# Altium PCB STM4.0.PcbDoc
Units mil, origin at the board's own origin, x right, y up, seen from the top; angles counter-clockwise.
Board outline 3545 x 2170 mil, 2 copper layers (Top Layer, Bottom Layer); 59 components, 66 nets, 302 pads, 59 vias.
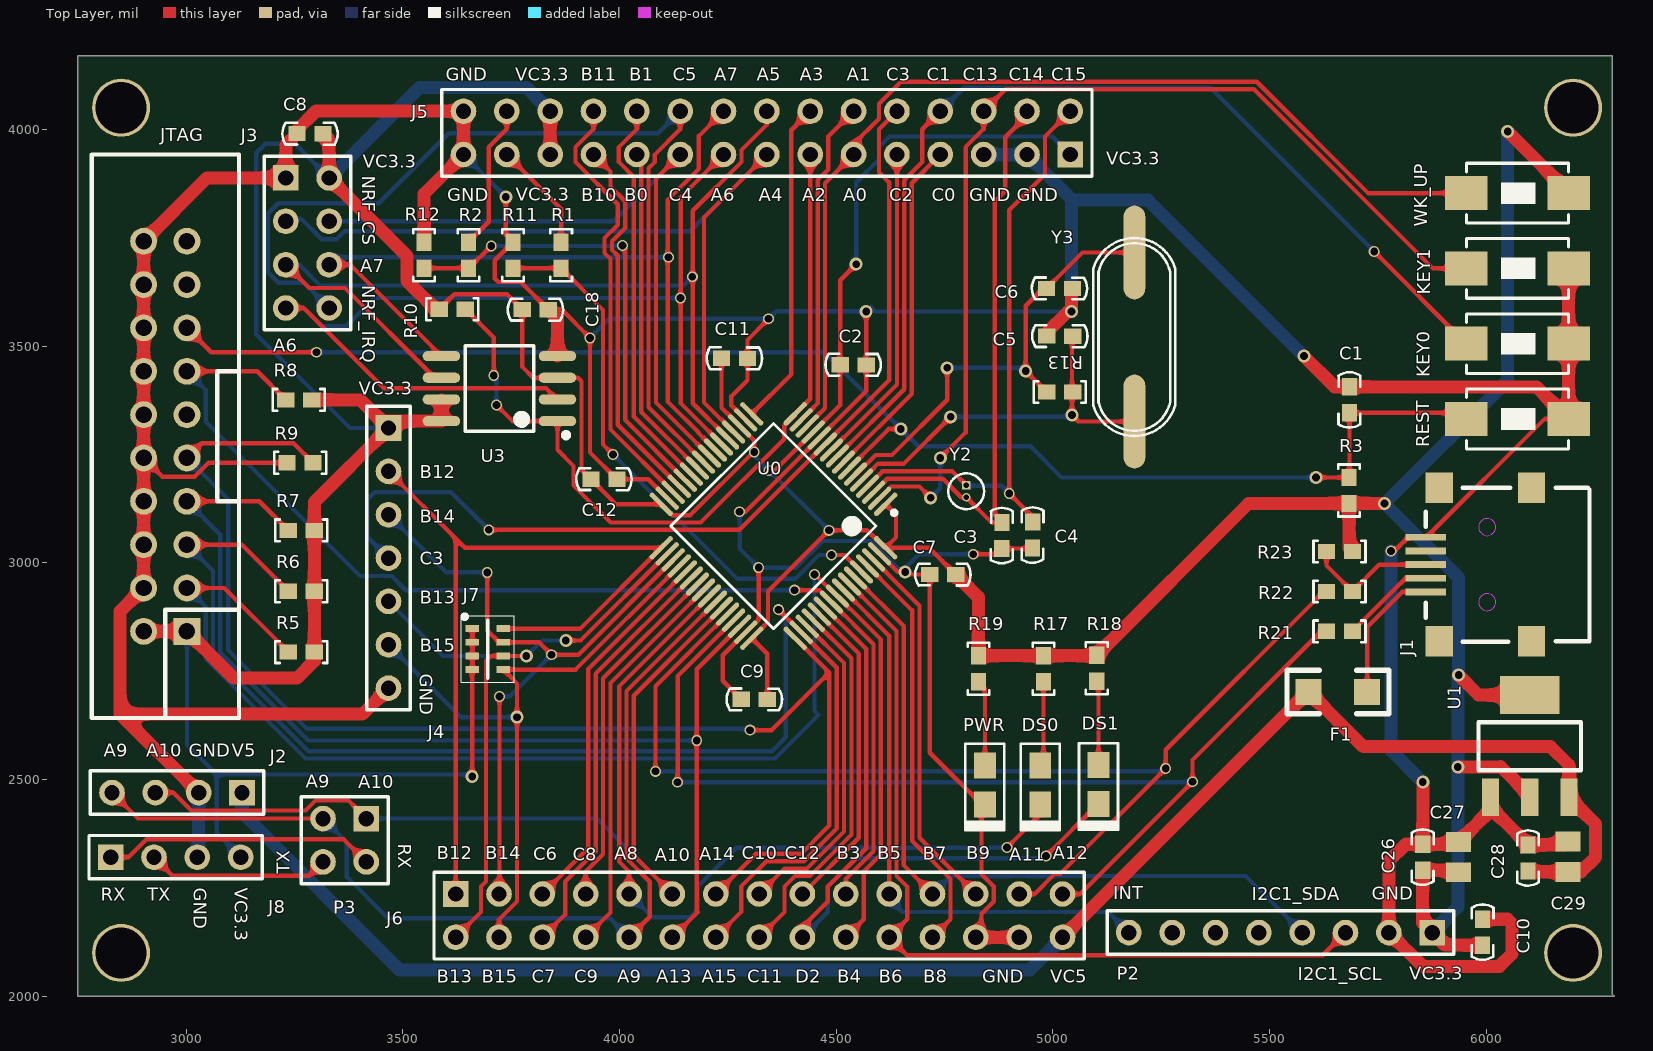
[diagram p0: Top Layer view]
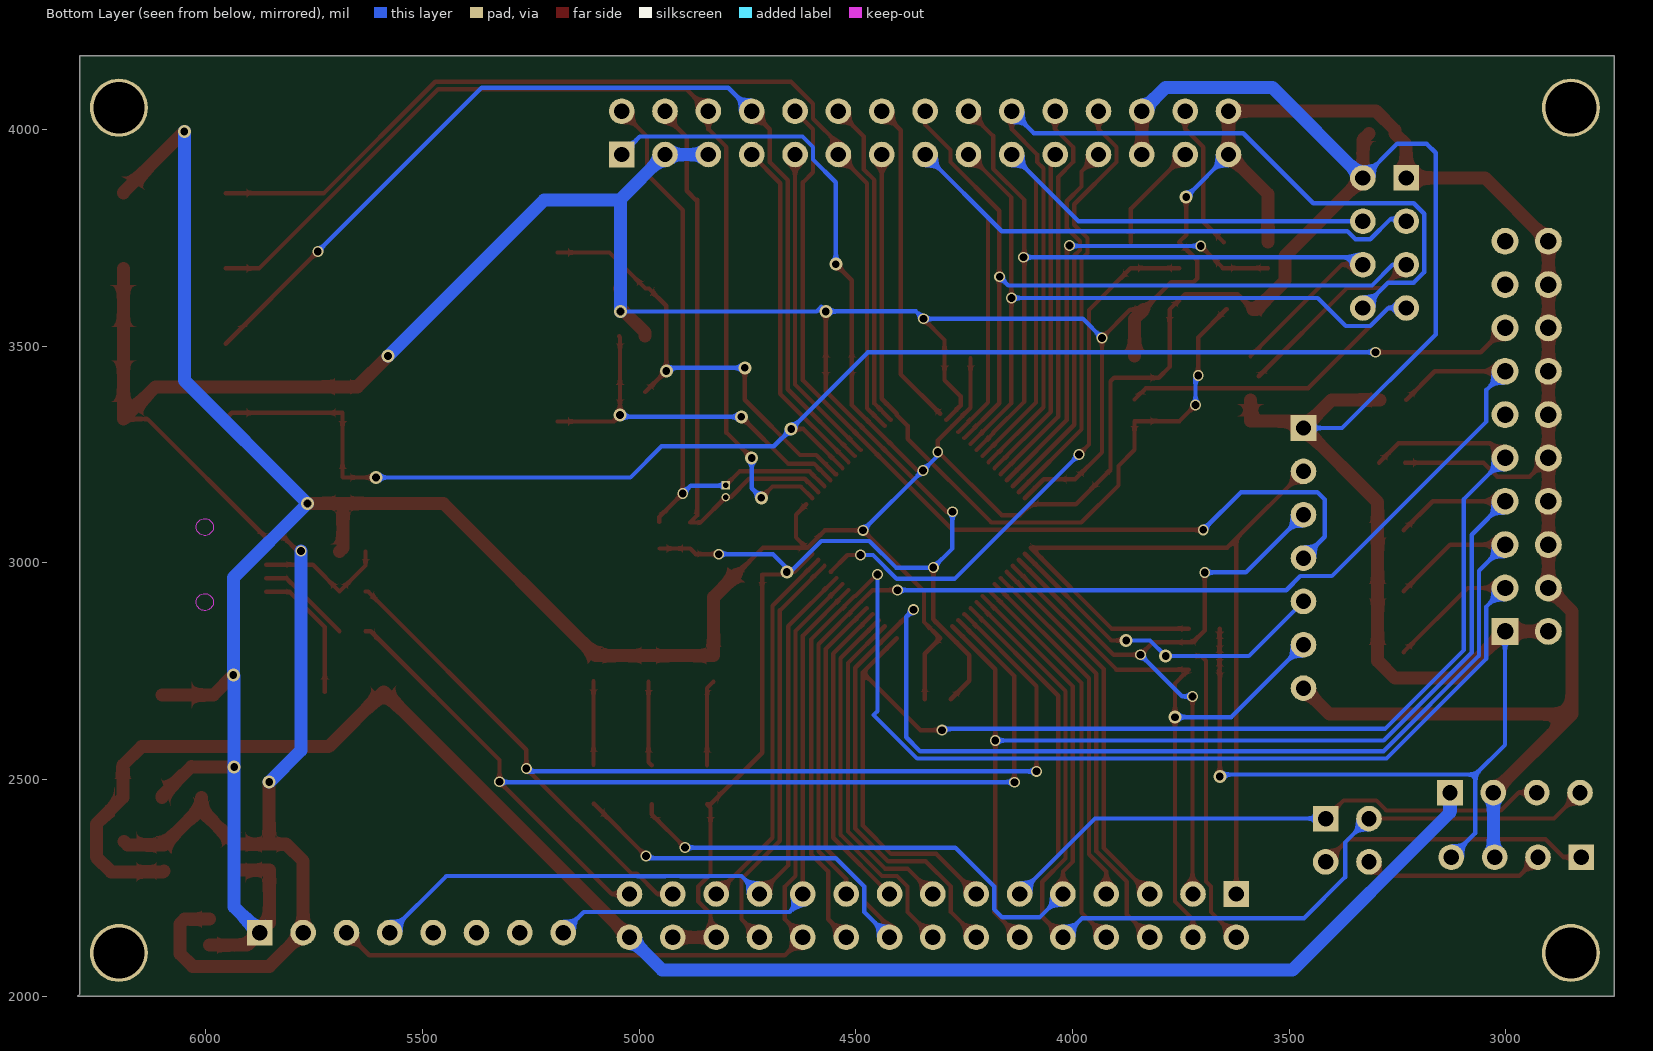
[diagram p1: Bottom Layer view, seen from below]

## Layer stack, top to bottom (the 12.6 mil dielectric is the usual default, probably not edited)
Top Solder: solder mask 0.4, Solder Resist, Dk 3.5
Top Layer: signal copper 1.4
Dielectric 1: dielectric 12.6, FR-4, Dk 4.8
Bottom Layer: signal copper 1.4
Bottom Solder: solder mask 0.4, Solder Resist, Dk 3.5

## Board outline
2750,4170 2750,2000 6295,2000 6290,2005 6290,4170 2750,4170

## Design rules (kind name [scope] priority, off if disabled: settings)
Clearance [All] p1: gap=7
PolygonConnect [All] p1: connectstyle=Relief reliefconductorwidth=10 reliefentries=4 polygonreliefangle="90 Angle" airgapwidth=10
RoutingVias [All] p1: holewidth=28 width=50 viastyle="Through Hole" minholewidth=28 minwidth=50 maxholewidth=28 maxwidth=50
SolderMaskExpansion [All] p1: expansion=4
Width [All] p1: maxlimit=30 minlimit=10 preferedwidth=10
30 further rules are at their usual default settings.

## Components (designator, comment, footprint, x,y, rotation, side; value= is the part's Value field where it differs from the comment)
C1 "Cap_0603" C0603 5684,3376 r90 top
C2 "Cap_0603" C0603 4539,3457 r0 top
C3 "CAP_0603" C0603 4882,3063 r90 top
C4 "CAP_0603" C0603 4953,3064 r90 top
C5 "Cap_0603" C0603 5015.89,3522.98 r0 top
C6 "Cap_0603" C0603 5015,3633 r0 top
C7 "Cap_0603" C0603 4746,2973 r180 top
C8 "Cap_0603" C0603 3286,3990 r180 top
C9 "Cap_0603" C0603 4311,2685 r180 top
C10 "Cap_0603" C0603 5991,2148 r270 top
C11 "Cap_0603" C0603 4265,3472 r0 top
C12 "Cap_0603" C0603 3964,3193 r0 top
C18 "Cap_0603" C0603 3806,3584 r180 top
C26 "Cap_0603" C0603 5853,2321 r90 top
C27 "106" LC-0805 5936,2321 r90 top
C28 "Cap_0603" C0603 6096,2319 r90 top
C29 "106" LC-0805 6188,2322 r90 top
DS0 "GREEN" SMD0805_LED_green 4971,2533 r270 top
DS1 "GREEN" SMD0805_LED_green 5105,2534 r270 top
F1 "500mA" FUSE_SMD1206 5590,2702 r0 top
J1 "usb" "MINI USB" 5860,2933 r180 top
J2 "USART1" HDR1X4 3129,2470 r180 top
J3 "NRF2401" HDR2X4 3230,3888 r270 top
J4 "OLED" HDR1X7 3467,3311 r270 top
J5 "Header 15X2" IDE15X2_2.54 5040,3942 r180 top
J6 "Header 15X2" IDE15X2_2.54 3622,2236 r0 top
J7 "Res_0603*4" RES_0603*4 3696,2801 r0 top
J8 "排母_2.54mm_4P" HDR1X4 2826,2321 r0 top
JTAG "10X2H" IDC20 3002,2842 r90 top
KEY0 "轻触开关/3x6x5 耐高温 环保" SW 5954.52,3505.67 r90 top
KEY1 "轻触开关/3x6x5 耐高温 环保" SW 5954.52,3679.33 r90 top
P2 "mpu6050" HDR1X8 5875,2147 r180 top
P3 "Header 2X2" HDR2X2 3416,2410 r180 top
PWR "RED" SMD0805_LED_green 4843,2533 r270 top
R1 "Res_0603" Res_0603 3865.33,3680 r90 top
R2 "Res_0603" Res_0603 3651.33,3740 r270 top
R3 "Res_0603" Res_0603 5683,3197 r270 top
R5 "Res_0603" Res_0603 3296,2794 r180 top
R6 "Res_0603" Res_0603 3296,2934.5 r180 top
R7 "Res_0603" Res_0603 3296,3075 r180 top
R8 "Res_0603" Res_0603 3290,3376 r180 top
R9 "Res_0603" Res_0603 3233,3231 r0 top
R10 "Res_0603" Res_0603 3644,3585 r180 top
R11 "Res_0603" Res_0603 3754,3740 r270 top
R12 "Res_0603" Res_0603 3549,3740 r270 top
R13 "Res_0603" Res_0603 4985.71,3393.98 r0 top
R17 "Res_0603" Res_0603 4978,2726 r90 top
R18 "Res_0603" Res_0603 5101,2727 r90 top
R19 "Res_0603" Res_0603 4828,2726 r90 top
R21 "Res_0603" Res_0603 5631,2842 r0 top
R22 "Res_0603" Res_0603 5631,2934 r0 top
R23 "Res_0603" Res_0603 5691,3026 r180 top
REST "轻触开关/3x6x5 耐高温 环保" SW 5954.52,3332 r90 top
U0 "STM32F103RCT6" LQFP64 4614,3135 r225 top
U1 "AMS1117-3.3" LC-SOT-223 6100,2577 r270 top
U3 "W25X16" LC-SOP-8_208mil 3723,3402 r90 top
WK_UP "轻触开关/3x6x5 耐高温 环保" SW 5954.52,3853 r90 top
Y2 "32.768KHZ±20ppm" TC-26 4800,3179 r270 top
Y3 "49SMD" 49SMD 5188,3521 r270 top

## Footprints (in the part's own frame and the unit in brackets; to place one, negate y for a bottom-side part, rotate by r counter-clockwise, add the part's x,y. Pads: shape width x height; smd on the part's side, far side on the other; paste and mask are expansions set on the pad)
49SMD [mil]
  oval 216.53x50 smd: 1(-195,0) 2(195,0)
  silkscreen extent -228,-95 228,94, body extent -264,-96 264,96, height 157
C0603 [mil]
  rect 40x35 smd: 1(-29.9,0.02) 2(30.1,-0.19)
  silkscreen extent -64,-25 64,25, body extent -31,-16 32,16, height 12
FUSE_SMD1206 [mil]
  rect 60x60 smd: 1(0,0) 2(135,0)
  silkscreen extent -50,-50 185,50, body extent 2,-33 128,33, height 40
HDR1X4 [mm]
  rect 1.5x1.5 hole 0.9: 1(0,0)
  round 1.5 hole 0.9: 2(2.54,0) 3(5.08,0) 4(7.62,0)
  silkscreen extent -1.27,-1.27 8.89,1.27, body extent -1.27,-1.27 8.89,1.27, height 8.38
HDR1X7 [mm] "Connector; Header; 7 Position"
  rect 1.5x1.5 hole 0.9: 1(0,0)
  round 1.5 hole 0.9: 2(2.54,0) 3(5.08,0) 4(7.62,0) 5(10.16,0) 6(12.7,0) 7(15.24,0)
  silkscreen extent -1.27,-1.27 16.51,1.27
HDR1X8 [mm]
  rect 1.5x1.5 hole 0.9: 1(0,0)
  round 1.5 hole 0.9: 2(2.54,0) 3(5.08,0) 4(7.62,0) 5(10.16,0) 6(12.7,0) 7(15.24,0) 8(17.78,0)
  silkscreen extent -1.27,-1.27 19.05,1.27, body extent -1.27,-1.27 19.05,1.27, height 8.38
HDR2X2 [mm] "Connector; Header; 2x2 Position"
  rect 1.5x1.5 hole 0.9: 1(0,0)
  round 1.5 hole 0.9: 2(0,2.54) 3(2.54,0) 4(2.54,2.54)
  silkscreen extent -1.27,-1.27 3.81,3.81
HDR2X4 [mm]
  rect 1.5x1.5 hole 0.9: 1(0,0)
  round 1.5 hole 0.9: 2(0,2.54) 3(2.54,0) 4(2.54,2.54) 5(5.08,0) 6(5.08,2.54) 7(7.62,0) 8(7.62,2.54)
  silkscreen extent -1.27,-1.27 8.89,3.81
IDC20 [mil]
  rect 62x62 hole 38: 1(0,0)
  round 62 hole 38: 2(0,100) 3(100,0) 4(100,100) 5(200,0) 6(200,100) 7(300,0) 8(300,100) 9(400,0) 10(400,100) 11(500,0) 12(500,100) 13(600,0) 14(600,100) 15(700,0) 16(700,100) 17(800,0) 18(800,100) 19(900,0) 20(900,100)
  silkscreen extent -200,-120 1100,220
IDE15X2_2.54 [mm]
  rect 1.5x1.5 hole 0.9: 1(0,0)
  round 1.5 hole 0.9: 2(0,-2.54) 3(2.54,0) 4(2.54,-2.54) 5(5.08,0) 6(5.08,-2.54) 7(7.62,0) 8(7.62,-2.54) 9(10.16,0) 10(10.16,-2.54) 11(12.7,0) 12(12.7,-2.54) 13(15.24,0) 14(15.24,-2.54) 15(17.78,0) 16(17.78,-2.54) 17(20.32,0) 18(20.32,-2.54) 19(22.86,0) 20(22.86,-2.54) 21(25.4,0) 22(25.4,-2.54) 23(27.94,0) 24(27.94,-2.54) 25(30.48,0) 26(30.48,-2.54) 27(33.02,0) 28(33.02,-2.54) 29(35.56,0) 30(35.56,-2.54)
  silkscreen extent -1.27,-3.81 36.83,1.27
LC-0805 [mm]
  rect 1.16x1.47 smd: 1(-0.89,0) 2(0.89,0)
LC-SOP-8_208mil [mm]
  oval 0.6x2.2 smd: 1(-1.905,-3.4) 2(-0.635,-3.4) 3(0.635,-3.4) 4(1.905,-3.4) 5(1.905,3.4) 6(0.635,3.4) 7(-0.635,3.4) 8(-1.905,3.4)
  silkscreen extent -2.88,-4.05 2.5,2
LC-SOT-223 [mm]
  rect 2.2x1 smd: 1(3,-2.3) 2(3,0) 3(3,2.3)
  rect 2.2x3.5 smd: 2(-3,0)
  silkscreen extent -1.4,-3 1.4,3, body extent -3.49,-3.24 3.49,3.24, height 1.64
LQFP64 [mm]
  oval 1.8x0.3 smd: 1(0,0) 2(0,-0.5) 3(0,-1) 4(0,-1.5) 5(0,-2) 6(0,-2.5) 7(0,-3) 8(0,-3.5) 9(0,-4) 10(0,-4.5) 11(0,-5) 12(0,-5.5) 13(0,-6) 14(0,-6.5) 15(0,-7) 16(0,-7.5) 33(11.1,-7.5) 34(11.1,-7) 35(11.1,-6.5) 36(11.1,-6) 37(11.1,-5.5) 38(11.1,-5) 39(11.1,-4.5) 40(11.1,-4) 41(11.1,-3.5) 42(11.1,-3) 43(11.1,-2.5) 44(11.1,-2) 45(11.1,-1.5) 46(11.1,-1) 47(11.1,-0.5) 48(11.1,0)
  oval 0.3x1.8 smd: 17(1.8,-9.3) 18(2.3,-9.3) 19(2.8,-9.3) 20(3.3,-9.3) 21(3.8,-9.3) 22(4.3,-9.3) 23(4.8,-9.3) 24(5.3,-9.3) 25(5.8,-9.3) 26(6.3,-9.3) 27(6.8,-9.3) 28(7.3,-9.3) 29(7.8,-9.3) 30(8.3,-9.3) 31(8.8,-9.3) 32(9.3,-9.3) 49(9.3,1.8) 50(8.8,1.8) 51(8.3,1.8) 52(7.8,1.8) 53(7.3,1.8) 54(6.8,1.8) 55(6.3,1.8) 56(5.8,1.8) 57(5.3,1.8) 58(4.8,1.8) 59(4.3,1.8) 60(3.8,1.8) 61(3.3,1.8) 62(2.8,1.8) 63(2.3,1.8) 64(1.8,1.8)
  silkscreen extent -0.12,-8 9.8,0.82, body extent 0.55,-8.75 10.55,1.25, height 1.6
"MINI USB" [mm]
  rect 1.6x1.8 smd: 0(-6.2,2.9) 0(-6.2,-6.1) 0(-0.8,2.9) 0(-0.8,-6.1)
  rect 2.4x0.4 smd: 1(0,0) 2(0,-0.8) 3(0,-1.6) 4(0,-2.4) 5(0,-3.2)
  Keep-Out Layer circle w0.025: c-3.6,-3.8 r0.5
  Keep-Out Layer circle w0.025: c-3.6,0.6 r0.5
  silkscreen extent -9.6,-6.1 0,2.92, body extent -9.2,-6.92 0,3.78, height 3.95
Res_0603 [mil]
  rect 40x35 smd: 1(0,0) 2(60,0)
  silkscreen extent -30,-25 90,25, body extent -1,-16 62,16, height 12
RES_0603*4 [mm]
  rect 0.8x0.4 smd: 1(-0.9,1.2) 2(-0.9,0.4) 3(-0.9,-0.4) 4(-0.9,-1.2) 5(0.9,-1.2) 6(0.9,-0.4) 7(0.9,0.4) 8(0.9,1.2)
  silkscreen extent -1.55,-1.95 1.55,2.02, body extent -0.8,-1.6 0.8,1.6, height 0.65
SMD0805_LED_green [mil]
  rect 60x50 smd: A(0,0) K(90,0)
  silkscreen extent -50,-45 150,45, body extent 5,-25 84,25, height 43
SW [mm]
  rect 2x2.5 smd: 1(0,0.025) 2(0,-5.975)
  silkscreen extent -1.75,-5.97 1.75,0.03, body extent -1.8,-6.97 1.8,1.03, height 2.4
TC-26 [mil]
  rect 19x19 hole 12: 1(0,0)
  round 19 hole 12: 2(27.56,0)
  silkscreen extent -28,-41 55,41

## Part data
C1 C2 C7 C9 C11 C12: library part 100nF_C0603_27010084, "贴片电容，100nF/50V，±10%，SMD0603，SAMSUNG"
C3 C4: library part 15pF_C0603_27010002, "贴片电容，15pF/50V，±5%，SMD0603，SAMSUNG"
C5 C6: library part 22pF_C0603_27010004, "贴片电容，22pF/50V，±5%，SMD0603，SAMSUNG"
C8 C10 C18 C26 C28: library part 0.1uF_C0603_27010044, "贴片电容，0.1uF/50V，±10%，SMD0603，SAMSUNG"
C27 C29: library part "CAPACITOR POL", "Capacitor"
DS0 DS1 PWR: library part LED绿色, "发光二极管，绿色，SMD0805，国产"
F1: library part NANOSMDC050F/13.2V-2, "贴片保险丝，NANOSMDC050F/13.2V-2,500MA，SMD1206，NANO"
J2: library part 排母_2.54mm_4P, "排母，间距2.54mm，1*4P，直插，国产"
J3: library part "HEADER 8", "8 Pin Header"
J4: library part "Header 7", "排母, 7-Pin,2.54MM"
J5 J6: "Header, 15-Pin, Dual row"
J7: library part 4.7K_0603*4_26050008, "电阻排，4.7K±5%，1/16W，0603*4，厚声"
J8: "排母，间距2.54mm，1*4P，直插，国产"
JTAG: library part "Header 10X2H", "Header, 10-Pin, Dual row, Right Angle"
KEY0 KEY1 REST WK_UP: library part 轻触开关, "轻触开关"
P2: library part MHDR1X8, "Header, 8-Pin"
P3: "Header, 2-Pin, Dual row"
R1 R2 R17 R18 R19: library part 510R_0603_26020037, "贴片电阻，510R±1%，1/10W，SMD0603，厚声"
R3 R10: library part 10K_0603_26020076, "贴片电阻，10K±0.1%，1/10W，SMD0603，厚声"
R5 R6 R7 R8 R9 R11 R12: library part 10K_0603_26020077, "贴片电阻，10K±1%，1/10W，SMD0603，厚声"
R13: library part 1M_0603_26020140, "贴片电阻，1M±1%，1/10W，SMD0603，RALEC"
R21 R22: library part 22R_0603_26020015, "贴片电阻，22R±1%，1/10W，SMD0603，RALEC"
R23: library part 1.5K_0603_26020049, "贴片电阻，1.5K±1%，1/10W，SMD0603，RALEC"
U0: library part STM32F103RBT6
U1: library part LT1085CM-3.3
Y2: "无源晶振，32.768KHZ±20ppm，TC-26，插件，2*6mm，国产"
Y3: library part 8MHz±20PPm_49SMD_25010002, "49SMD，8MHz±20PPm，49SMD，LC"

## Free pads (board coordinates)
  round 133.86 hole 118.11: ""(2850,2100) ""(2850,4050) ""(6200,2100) ""(6200,4050)

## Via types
v1: diameter 25, hole 18, Top Layer to Bottom Layer, 36 vias
v2: diameter 30, hole 18, Top Layer to Bottom Layer, 23 vias

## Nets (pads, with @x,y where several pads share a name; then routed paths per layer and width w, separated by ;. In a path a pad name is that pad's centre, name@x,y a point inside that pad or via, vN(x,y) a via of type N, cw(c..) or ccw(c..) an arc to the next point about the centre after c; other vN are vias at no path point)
ADC0: J5.11 U0.14 WK_UP.1 | length 2294.3
  Top Layer w10: U0.14 4474,3356.91 4474,3876 J5.11 4540,3966.04 4598.47,4024.51 4598.47,4059.2 4649.27,4110 5470.04,4110 5727.04,3853 WK_UP.1
ADC1: J5.12 U0.15 | length 762.2
  Top Layer w10: U0.15 4457,3367.74 4457,3883.04 4481.53,3907.57 4481.53,3983.53 J5.12
ADC2: J5.13 R10.1 U0.16 U3.1 | length 1853.5
  Top Layer w10: R10.1 3645,3585 3710,3520 v1(3710,3432) ; v1(3716,3364) 3753,3327 U3.1 3856.86,3260.73 3894,3223.59 3894,3178.65 3979.52,3093.13 4187.13,3093.13 4380.34,3286.34 4380.34,3316.41 4405.21,3341.27 U0.16 4440,3378.58 J5.13
  Bottom Layer w10: v1(3710,3432) 3716,3426 v1(3716,3364)
ADC3: J5.14 U0.17 | length 754.1
  Top Layer w10: U0.17 4396,3434.8 4396,3998 J5.14
ADC10: J5.7 U0.8 | length 802.1
  Top Layer w10: U0.8 4674,3389.87 4674,3876 J5.7
ADC12: J5.9 U0.10 | length 744.4
  Top Layer w10: U0.10 4640,3411.55 J5.9
BOOT0: R1.1 R11.2 U0.60 | length 1324
  Top Layer w10: R11.2 R1.1 3962,3583.33 3962,3273 v1(3985,3250) ; v1(4489,3018) 4520,3018 4519.71,3017.71 U0.60 U0.60@4556.9,2979.1
  Bottom Layer w10: v1(3985,3250) 4272,2963 4405.35,2963 4460.35,3018 v1(4489,3018)
BOOT1: R2.2 R12.2 U0.28 | length 1080.9
  Top Layer w10: R12.2 R2.2 3653,3680 v1(3704,3731) ; v1(4007,3732) 4013,3726 4013,3329.55 U0.28
  Bottom Layer w10: v1(3704,3731) 4006,3731 v1(4007,3732)
GND: C1.2 C2.2 C3.1 C4.1 C5.1 C6.2 C7.2 C8.2 C9.2 C10.1 C11.2 C12.2 C18.1 C26.2 C27.2 C28.2 C29.2 J1.5 J2.2 J3.1 J4.7 J5.3 J5.5 J5.29 J5.30 J6.26 J6.28 J8.3 JTAG.4 JTAG.6 JTAG.8 JTAG.10 JTAG.12 JTAG.14 JTAG.16 JTAG.18 JTAG.20 KEY0.2 KEY1.2 P2.2 PWR.K R9.1 R11.1 R12.1 REST.2 U0.12 U0.18 U0.31 U0.47 U0.63 U1.1 U3.4 | length 14158.3
  Top Layer w10: JTAG.10 2945,3199 3019.81,3199 3051.81,3231 R9.1 ; v2(3737.69,3844.31) 3737.69,3756.31 R11.1 3712,3698 3712,3656 3720,3648 3771.88,3648 C18.1 3867.02,3583.98 v1(3932,3519) 3932,3254.91 C12.2 4066.23,3192.81 U0.31 ; v1(4277,3118) 4290.77,3118 U0.12 4569.1,3396.33 C2.2 v2(4569.1,3580.1) ; C9.2 4238,2728.09 4238,2786.84 U0.47 4321,2869.84 v1(4321,2989) ; U0.18 4258,3362.94 4258,3384 4295.1,3421.1 C11.2 4295.1,3514.1 v1(4344,3563) ; U0.63 4641.94,2979 v2(4659,2979) 4664.81,2973.19 C7.2 4715.9,2562.1 4835,2443 PWR.K 4835,2435 4835,2281.73 4863.53,2253.2 4863.53,2218.8 4835,2190.27 4835,2149 J6.26 ; v1(4816,3020) 4868.88,3020 C3.1 C4.1@4951.98,3033.1 ; v1(5780,3027) 5787.42,3027 5819.41,3058.99 J1.5 5861.22,3058.99 6134.24,3332 REST.2
  Top Layer w30: J2.2 2848,2651 ; J4.7 3407,2651 2848,2651 ; R12.1 3549,3851 J5.29 J5.30 3299.3,4042 3255.9,3998.59 C8.2 3230,3964.29 J3.1 3048,3888 JTAG.20 JTAG.18 JTAG.16 JTAG.14 JTAG.12 JTAG.10 JTAG.8 JTAG.6 JTAG.4 2848,2888 2848,2651 ; C18.1 3856.86,3563.02 U3.4 ; J6.26 J6.28 ; C5.1 4986,3531.4 5034.59,3580 v2(5043,3580) 5043,3630.71 C6.2 ; v2(5579,3477) 5649.9,3406.1 C1.2 6115.64,3406.1 REST.2 KEY0.2 KEY1.2 ; v2(5853.19,2494.19) C26.2 ; C10.1 6048.1,2177.9 6059,2167 6059,2098 6030,2069 5853,2069 P2.2 5775,2312 5814.1,2351.1 C26.2 ; U1.1 U1.1@6009.45,2435.85 ; C29.2 6180.06,2349.1 C28.2 U1.1@6009.45,2435.85 ; C26.2 5931.06,2351.1 C27.2 6009.45,2429.49 U1.1@6009.45,2435.85
  Bottom Layer w10: J5.29 v2(3737.69,3844.31) ; v1(3932,3519) 3976,3563 v1(4344,3563) 4361.1,3580.1 v2(4569.1,3580.1) 4579.51,3590.51 4590.02,3580 v2(5043,3580) ; v1(4277,3118) 4277,3033 v1(4321,2989) 4407.31,2989 4468.81,3050.5 4579.5,3050.5 4651,2979 v2(4659,2979) 4659,2988 4691,3020 v1(4816,3020)
  Bottom Layer w30: J8.3 3029,2324 J2.2 ; J5.5 J5.3 5045.1,3836.9 ; v2(5043,3580) 5043,3834.79 5045.1,3836.9 ; v2(5579,3477) 5219.1,3836.9 5045.1,3836.9 ; v1(5780,3027) 5780,2567.38 v2(5853.19,2494.19)
I2C1_SCL: J6.22 P2.3 U0.58 | length 1979.5
  Top Layer w10: U0.58 4639,2842.75 4639,2277.73 4663.53,2253.2 4663.53,2177.53 J6.22 4663.53,2094.47 5622.47,2094.47 P2.3
I2C1_SDA: J6.23 P2.4 U0.59 | length 1727.9
  Top Layer w10: U0.59 4656,2853.59 4656,2302 J6.23
  Bottom Layer w10: J6.23 4763.53,2277.53 4839.2,2277.53 4839.73,2277 4904.27,2277 4904.8,2277.53 4939.2,2277.53 4939.73,2277 5004.27,2277 5004.8,2277.53 5444.47,2277.53 P2.4
INT: J6.21 P2.8 U0.57 | length 1341.3
  Top Layer w10: U0.57 4622,2831.91 J6.21
  Bottom Layer w10: J6.21 4622,2225 4652.53,2194.47 5127.53,2194.47 P2.8
JTCK: J6.13 JTAG.9 R9.2 U0.49 | length 3116.8
  Top Layer w10: JTAG.9 3036,3276 3248,3276 R9.2 ; J6.13 4314.53,2328.53 4418.36,2328.53 4484,2394.17 4484,2747.2 ; v1(4301,2614) 4350.8,2614 4484,2747.2 ; U0.49 4484,2747.2
  Bottom Layer w10: JTAG.9 3097,3147 3097,2799.12 3279.12,2617 4298,2617 v1(4301,2614)
JTDI: J6.14 JTAG.5 R6.2 U0.50 | length 3264.5
  Top Layer w10: JTAG.5 3128.5,3042 R6.2 ; J6.14 4280.47,2194.47 4280.47,2253.2 4338.8,2311.53 4425.4,2311.53 4501,2387.12 4501,2758.04 U0.50 v1(4367.04,2892)
  Bottom Layer w10: JTAG.5 3062,2982 3062,2786.04 3282.54,2565.5 4351.46,2565.5 4383.48,2597.52 4383.48,2875.56 v1(4367.04,2892)
JTDO: J6.19 JTAG.13 R8.2 U0.55 | length 2745.7
  Top Layer w10: JTAG.13 3164,3442 R8.2 ; v1(4404,2937) 4461.23,2937 U0.55 4586,2812.23 4586,2334.69 4522,2270.69 J6.19
  Bottom Layer w10: JTAG.13 3045,3399 3045,3326 3401.53,2969.47 3474.53,2969.47 3507,2937 v1(4404,2937)
JTMS: J6.12 JTAG.7 R7.2 U0.46 | length 2609.8
  Top Layer w10: JTAG.7 3169,3142 R7.2 ; J6.12 4180.47,2194.47 4178,2196.94 v1(4178,2590) 4178,2754.68 U0.46
  Bottom Layer w10: JTAG.7 3079,3065 3079,2793.08 3282.08,2590 v1(4178,2590)
JTRST: J6.20 JTAG.3 R5.2 U0.56 | length 3290.7
  Top Layer w10: JTAG.3 3088,2942 R5.2 ; v1(4450,2973) 4451,2973 4500.58,2923.42 U0.56 4603,2823.07 4603,2327.65 4563.53,2288.17 4563.53,2177.53 J6.20
  Bottom Layer w10: JTAG.3 3045,2899 3045,2779 3275.5,2548.5 4358.5,2548.5 4459,2649 4450,2658 v1(4450,2973)
KEY0: J5.8 KEY0.1 U0.9 | length 2374.4
  Top Layer w10: U0.9 4657,3400.71 4657,3883.04 4698.47,3924.51 4698.47,4000.47 J5.8 ; v1(5741,3718.19) KEY0.1
  Bottom Layer w10: J5.8 4794,4096 5363.19,4096 v1(5741,3718.19)
KEY1: J5.6 KEY1.1 U0.2 | length 2388.4
  Top Layer w10: U0.2 4627.16,3176 4692,3176 v2(4718,3150) ; v2(4740,3242) 4798.47,3300.47 4798.47,3959.2 4840,4000.73 J5.6 4891,4093 5463,4093 5876.67,3679.33 KEY1.1
  Bottom Layer w10: v2(4718,3150) 4740,3172 v2(4740,3242)
LED0: DS0.K J6.9 U0.41 | length 1907.2
  Top Layer w10: J6.9 4022,2287.92 3999,2310.92 3999,2714.87 U0.41 ; v1(4894,2343) 4971,2420 DS0.K
  Bottom Layer w10: J6.9 4076,2182 4162,2182 4180.47,2200.47 4180.47,2253.2 4270.27,2343 v1(4894,2343)
LED1: DS1.K J6.18 U0.54 | length 1704.5
  Top Layer w10: J6.18 4422,2160.33 4480.47,2218.8 4480.47,2253.2 4569,2341.73 4569,2801.39 U0.54 ; v1(4984,2324) 5104,2444 DS1.K
  Bottom Layer w10: J6.18 4480.47,2194.47 4480.47,2253.2 4545.77,2318.5 4978.5,2318.5 v1(4984,2324)
NetDS0_A: DS0.A R17.1 | length 195.9
  Top Layer w10: DS0.A 4978,2540 R17.1
NetDS1_A: DS1.A R18.1 | length 193
  Top Layer w10: DS1.A R18.1@5105,2727
NetF1_2: F1.2 J1.1 | length 318.5
  Top Layer w10: F1.2 5725,2851.96 5806.04,2933 J1.1
NetJ1_2: J1.2 R21.2 | length 219.7
  Top Layer w10: R21.2 5813.5,2964.5 J1.2
NetJ1_3: J1.3 R22.2 R23.2 | length 311.5
  Top Layer w10: R23.2 5631,2994 R22.2 5752.99,2995.99 J1.3
NetJ5_27: J5.27 R1.2 | length 253.9
  Top Layer w10: J5.27 3865.33,3816.67 R1.2
NetJ5_28: J5.28 R2.1 | length 338.7
  Top Layer w10: R2.1 3698.47,3787.14 3698.47,3959.2 3740,4000.73 J5.28
NetPWR_A: PWR.A R19.1 | length 199.2
  Top Layer w10: R19.1 4843,2711 PWR.A
"NRF CE": J3.3 J5.15 U0.20 | length 1940.7
  Top Layer w10: U0.20 4195,3370.26 4195,3797 J5.15
  Bottom Layer w10: J3.3 3235.14,3793.14 3266.14,3793.14 3312.8,3746.47 3347.2,3746.47 3365.73,3765 4163,3765 J5.15
"NRF CS": J3.4 J5.19 U0.24 | length 1643.8
  Top Layer w10: J5.19 4084,3886 4084,3369.91 U0.24
  Bottom Layer w10: J3.4 3986,3788 J5.19
"NRF IRQ": J3.8 J5.20 U0.25 | length 2252.1
  Top Layer w10: J5.20 4140,4000.73 4081.53,3942.26 4081.53,3924.8 4067,3910.27 4067,3359.07 U0.25
  Bottom Layer w10: J3.8 3271.53,3646.47 3212.8,3646.47 3188.47,3670.8 3188.47,3805.2 3212.8,3829.53 3444.47,3829.53 3605.94,3991 4089,3991 J5.20
OSCIN1: C3.2 J5.4 U0.3 Y2.2 | length 1337
  Top Layer w10: U0.3 4617.32,3194 4746,3194 4788.56,3151.44 Y2.2 4858.34,3093.1 C3.2 4866,3109.29 4866,3838 ; 4866,3834.31 4890,3858.31 ; 4890,3862 4890,3981.73 4940,4031.73 J5.4
OSCIN2: C5.2 R13.2 U0.5 Y3.2 | length 881.8
  Top Layer w10: U0.5 4596.64,3229 4656,3229 v2(4764,3337) ; C5.2 5044,3520.79 v2(5044,3341) 5059,3326 Y3.2
  Bottom Layer w10: v2@4759,3341 4763,3337 v2(4764,3337) v2@5040,3337
OSCOUT1: C4.2 J5.2 U0.4 Y2.1 | length 1390.8
  Top Layer w10: U0.4 4606.48,3211 4768,3211 Y2.1 ; C4.2 4953.19,3105.81 v1(4899,3160) 4899,3813.81 4981.53,3896.34 4981.53,3983.53 J5.2
  Bottom Layer w10: Y2.1 4801,3178 4881,3178 v1(4899,3160)
OSCOUT2: C6.1 R13.1 U0.6 Y3.1 | length 1061.7
  Top Layer w10: U0.6 4546.92,3204.6 4591.32,3249 4628.82,3249 4756,3376.18 v2(4756,3450) ; R13.1 v2(4937,3442.69) 4937,3593 4977.02,3633.02 C6.1 5068.08,3716 Y3.1
  Bottom Layer w10: v2(4756,3450) 4929.69,3450 v2(4937,3442.69)
PA5: J3.5 J5.16 U0.21 U3.6 | length 2271.2
  Top Layer w10: J3.5 3284,3634 3366.86,3634 U3.6@3570.36,3430.5 ; U0.21 4169,3368.42 4169,3812.27 4281.53,3924.8 4281.53,3952.53 4340,4011 J5.16
  Bottom Layer w10: J3.5 3261,3688 3309,3640 4148,3640 v1(4168,3660)
PA6: J3.7 J5.17 U0.22 U3.2 | length 2417.1
  Top Layer w10: J3.7 3271.27,3588 3456.08,3403.19 3830.67,3403.19 U3.2 ; U0.22 4141,3368.59 v1(4141,3611) 4141,3843 J5.17
  Bottom Layer w10: J3.7 3271.27,3588 3312.8,3546.47 3369.47,3546.47 3434,3611 v1(4141,3611)
PA7: J3.6 J5.18 U0.23 U3.5 | length 2017.5
  Top Layer w10: J3.6 3378.14,3688 U3.5 ; U0.23 4183.1,3298.64 4183.1,3299.92 4111,3372.03 4111,3837.04 4183.1,3909.14 4183.1,3985.1 J5.18
  Bottom Layer w10: J3.6 3347,3705 v1(4113,3705)
PA9: J2.4 J6.10 P3.3 U0.42 | length 2278.7
  Top Layer w10: J2.4 2889,2410 P3.3 ; J6.10 4069.58,2183.58 4069.58,2264.37 4016,2317.96 4016,2704.03 U0.42
  Bottom Layer w10: P3.3 3371,2355 3371,2275 3466,2180 3978,2180 J6.10
PA10: J2.3 J6.11 P3.1 U0.43 | length 2089.3
  Top Layer w10: J2.3 2970.27,2470 3011.8,2428.47 3275.74,2428.47 3298.8,2451.53 3374.47,2451.53 P3.1 ; J6.11 4033,2325 4033,2693.19 U0.43
  Bottom Layer w10: P3.1 3948,2410 J6.11
PA11: J6.27 R22.1 U0.44 | length 2634.9
  Top Layer w10: v1(4083,2519) 4083,2715 4086,2718 4086,2718.36 U0.44 ; J6.27 4958,2236 5005,2283 5017.53,2283 v1(5260,2525.47) 5260,2569 5625,2934 R22.1
  Bottom Layer w10: v1(4083,2519) 5253.53,2519 v1(5260,2525.47)
PA12: J6.29 R21.1 U0.45 | length 2507.4
  Top Layer w10: 4133.74,2738.26 U0.45 ; v1(4134,2494) 4134,2739 ; J6.29@5022,2237.96 J6.29 5063,2236 v1(5322,2495) 5322,2545 5619,2842 R21.1
  Bottom Layer w10: v1(4134,2494) v1@5322,2494
PB0: J5.21 U0.26 | length 781.4
  Top Layer w10: J5.21 4050,3932 4050,3348.23 U0.26
PB1: J5.22 U0.27 | length 923.9
  Top Layer w10: J5.22 4040,4000.73 3998.47,3959.2 3998.47,3924.8 4033,3890.27 4033,3337.39 U0.27
PB8: J6.24 U0.61 | length 953.5
  Top Layer w10: U0.61 4675,2890.26 4675,2358.96 4763.53,2270.43 4763.53,2177.53 J6.24
PB9: J6.25 U0.62 | length 868.6
  Top Layer w10: U0.62 4692,2901.1 4692,2366 J6.25
PB10: J5.23 U0.29 | length 872.5
  Top Layer w10: J5.23 3979,3903 3979,3868.31 4013,3834.31 4013,3772.65 3982.5,3742.15 3982.5,3721.85 3996,3708.35 3996,3318.71 U0.29
PB11: J5.24 U0.30 | length 1015.1
  Top Layer w10: J5.24 3940,4000.73 3898.47,3959.2 3898.47,3924.8 3996,3827.27 3996,3779.69 3965.5,3749.19 3965.5,3714.81 3979,3701.31 3979,3307.88 U0.30
PB12: J4.2 J6.1 J7.8 U0.33 | length 1964.2
  Top Layer w10: J4.2 3622,3056 ; J6.1 3622,3056 ; J7.8 3909.66,2848.24 U0.33 3643.22,3034.78 3622,3056
PB13: J4.5 J6.2 J7.6 U0.34 | length 1557.8
  Top Layer w10: J6.2 3680.47,2194.47 3680.47,2253.2 3692,2264.73 3692,2774 3703.25,2785.25 J7.6 3731.68,2785 v2(3785,2785) ; v2(3876,2821) 3910.26,2821 U0.34
  Bottom Layer w10: J4.5 3593,2785 v2(3785,2785) 3821,2821 v2(3876,2821)
PB14: J4.3 J6.3 J7.7 U0.35 | length 1576.1
  Top Layer w10: v1(3695,2978) 3695,2844.08 3722.34,2816.74 J7.7 3814.26,2816.74 v1(3843,2788) 3905.09,2788 U0.35 ; J6.3 3723,2237 v1(3723,2692)
  Bottom Layer w10: J4.3 3600,2978 v1(3695,2978) ; v1(3723,2692) 3747,2692 v1(3843,2788)
PB15: J4.6 J6.4 J7.5 U0.36 | length 1519.6
  Top Layer w10: J6.4 3722,2177.27 3763.53,2218.8 v2(3763.53,2644) 3763.53,2721.66 J7.5 3898.69,2753.75 U0.36
  Bottom Layer w10: J4.6 3634,2644 v2(3763.53,2644)
PC3: J4.4 J5.10 U0.11 | length 2192.9
  Top Layer w10: v1(3698.13,3076.13) 4276.75,3076.13 U0.11 4622,3421.39 4622,3877.74 4598.47,3901.27 4598.47,4000.47 J5.10
  Bottom Layer w10: J4.4 3418,3060 3418,3146 3435,3163 3611.27,3163 v1(3698.13,3076.13)
PC6: J6.5 U0.37 | length 879.7
  Top Layer w10: J6.5 3928,2342 3928,2755.23 U0.37
PC7: J6.6 U0.38 | length 971.6
  Top Layer w10: J6.6 3874.41,2188.41 3874.41,2264.37 3945,2334.96 3945,2744.39 U0.38
PC8: J6.7 U0.39 | length 822
  Top Layer w10: J6.7 3922,2287.92 3962,2327.92 3962,2733.55 U0.39
PC9: J6.8 U0.40 | length 913.9
  Top Layer w10: J6.8 3979,2193 3979,2722.71 U0.40
PC10: J6.15 U0.51 | length 764.6
  Top Layer w10: J6.15 4380.53,2294.53 4432.44,2294.53 4518,2380.08 4518,2768.87 U0.51
PC11: J6.16 U0.52 | length 876.8
  Top Layer w10: J6.16 4380.47,2194.47 4380.47,2253.2 4404.8,2277.53 4439.49,2277.53 4535,2373.04 4535,2779.71 U0.52
PC12: J6.17 U0.53 | length 737.3
  Top Layer w10: J6.17 4552,2366 4552,2790.55 U0.53
RESET: C1.1 JTAG.15 R3.1 REST.1 U0.7 | length 3404.8
  Top Layer w10: JTAG.15 3058,3486 v1(3301,3486) ; U0.7 4620.97,3309 v2(4649,3309) ; v2(5607,3197) R3.1 5683.98,3197.98 C1.1 5939.42,3346.1 REST.1
  Bottom Layer w10: v1(3301,3486) 4472,3486 v2(4649,3309) 4689,3269 4948,3269 5020,3197 v2(5607,3197)
RX: J8.1 P3.2 | length 629
  Top Layer w10: J8.1 2867.27,2321 2908.8,2362.53 3363.47,2362.53 P3.2
TX: J8.2 P3.4 | length 421.1
  Top Layer w10: J8.2 2969,2278 3284,2278 P3.4
VCC3.3: C2.1 C7.1 C8.1 C9.1 C10.2 C11.1 C12.1 C18.2 C26.1 C27.1 J3.2 J4.1 J5.1 J5.25 J5.26 J7.1 J7.2 J7.3 J7.4 J8.4 JTAG.1 JTAG.2 P2.1 R3.2 R5.1 R6.1 R7.1 R8.1 R10.2 R17.2 R18.2 R19.2 R23.1 U0.1 U0.13 U0.19 U0.32 U0.48 U0.64 U1.2 U3.3 U3.7 U3.8 WK_UP.2 | length 13584.9
  Top Layer w10: R10.2 3619,3620 3740.09,3620 C18.2 3775.9,3452.1 3801,3427 U3.3 3904,3427 3912.17,3418.83 3912.17,3214.96 C12.1 3992.12,3135 U0.32 4121.06,3110.13 4163.13,3110.13 4309,3256 v1(4311,3256) 4311,3282.1 U0.19 4235.1,3358 C11.1 ; v2(3660,2507) 3660,2748.32 3663,2751.32 J7.4 J7.3 J7.2 J7.1 ; C9.1 4340.9,2790.08 U0.48 4342.54,2863.54 4342.54,2934.54 v1(4483,3075) 4571.26,3075 4611.48,3034.78 U0.64 ; v1(4345,3213) 4357.93,3213 U0.13 4509.1,3364.17 C2.1 4509.1,3652.1 v2(4546,3689) ; U0.1 4638,3111 4638,3058.78 U0.64 ; C7.1 4714.1,3034.78 U0.64
  Top Layer w30: JTAG.2 JTAG.1 3110,2734 3256,2734 3296,2774 R5.1 R6.1 R7.1 3296,3140 J4.1 ; R8.1 3402,3376 3451,3327 U3.8 U3.7@3589.14,3376.19 ; C8.1 3330,3975.88 J3.2 3509.5,3708.5 3509.5,3650.89 3575.39,3585 R10.2 ; J5.25 J5.26 ; C7.1 4828,2920.88 R19.2 R17.2 R18.2@5100,2786 ; R18.2 5451,3137 R3.2 ; R23.1 5683,3034 R3.2 ; v2(5765,3137) R3.2 ; C27.1@5930.86,2291.1 C26.1 5852.98,2169.02 P2.1 5904.1,2117.9 C10.2 ; v2(5934,2529) 6031.44,2529 6032.44,2530 6100,2462.44 U1.2@6100,2458.89 ; v2(5936,2741) 5981.89,2695.11 U1.2@6100,2695.11 ; v2(6049,3995) 6189.74,3854.26 WK_UP.2
  Bottom Layer w10: JTAG.1 3002,2580.06 3070.53,2511.53 ; J8.4 3070.53,2376.47 3070.53,2511.53 ; J3.2 3251,3967 3183,3967 3162,3946 3162,3527 3378,3311 J4.1 ; v2(3660,2507) 3655.47,2511.53 3070.53,2511.53 ; v1(4311,3256) 4309,3256 4305.5,3252.5 v1(4345,3213) v1(4483,3075) ; v2(4546,3689) 4546,3878 4598.47,3930.47 4598.47,3959.2 4622.8,3983.53 4998.47,3983.53 J5.1
  Bottom Layer w30: J3.2 3539,4097 3785,4097 J5.26 ; P2.1 5934,2206 v2(5934,2529) 5934,2739 v2(5936,2741) 5936,2966 v2(5765,3137) 6049,3421 v2(6049,3995)
VCC5: C28.1 C29.1 F1.1 J2.1 J6.30 U1.3 | length 4002.1
  Top Layer w30: J6.30 5588,2702 F1.1 5716,2576 6148,2576 6190.55,2533.45 U1.3 6252,2397.44 6252,2321 6217.96,2286.96 C29.1 6098.12,2286.96 C28.1
  Bottom Layer w30: J2.1 3129,2424.13 3492.13,2061 4947,2061 J6.30
pads on no net: J1.0 J1.4 JTAG.11 JTAG.17 JTAG.19 P2.5 P2.6 P2.7

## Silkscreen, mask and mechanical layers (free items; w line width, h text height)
Top Overlay:
  text "GND" at 3599,4112 h30
  text "VC3.3" at 3760,4112 h30
  text "B11" at 3911,4112 h30
  text "B1" at 4023,4112 h30
  text "C5" at 4123,4112 h30
  text "A7" at 4219,4112 h30
  text "A5" at 4317,4112 h30
  text "A3" at 4416,4112 h30
  text "A1" at 4524,4112 h30
  text "C3" at 4615,4112 h30
  text "C1" at 4709,4112 h30
  text "C13" at 4792,4112 h30
  text "C14" at 4898,4112 h30
  text "C15" at 4996,4112 h30
  text "VC3.3" at 5123,3918 h30
  text "VC3.3" at 3408,3911 h30
  text "NRF_CS" at 3407,3893 h30 r270
  text "VC3.3" at 3761,3835 h30
  text "GND" at 3602,3834.31 h30
  text "B10" at 3912,3834.31 h30
  text "B0" at 4011,3834.31 h30
  text "C4" at 4114,3834.31 h30
  text "A6" at 4210,3834.31 h30
  text "A4" at 4321,3834.31 h30
  text "A2" at 4422,3834.31 h30
  text "A0" at 4516,3834.31 h30
  text "C2" at 4622,3834.31 h30
  text "C0" at 4720,3834.31 h30
  text "GND" at 4807,3834.31 h30
  text "GND" at 4917,3834.31 h30
  text "A7" at 3402,3671 h30
  text "NRF_IRQ" at 3407,3641 h30 r270
  text "A6" at 3201,3487 h30
  text "VC3.3" at 3398,3388 h30
  text "B12" at 3539,3195 h30
  text "B14" at 3539,3092 h30
  text "C3" at 3539,2996 h30
  text "B13" at 3539,2906 h30
  text "B15" at 3539,2795 h30
  text "GND" at 3539,2744 h30 r270
  text "A9" at 2810,2553 h30
  text "A10" at 2908.33,2553 h30
  text "GND" at 3006.67,2553 h30
  text "V5" at 3105,2553 h30
  text "B12" at 3578,2316 h30
  text "B14" at 3690,2316 h30
  text "C10" at 4282,2316 h30
  text "C12" at 4381,2316 h30
  text "B3" at 4501,2316 h30
  text "B5" at 4595,2316 h30
  text "B9" at 4800,2316 h30
  text "A12" at 4999,2316 h30
  text "A8" at 3988,2315 h30
  text "B7" at 4699,2315 h30
  text "C6" at 3801,2314 h30
  text "A14" at 4184,2314 h30
  text "C8" at 3892,2313 h30
  text "A11" at 4899,2313 h30
  text "A10" at 4081,2312 h30
  text "GND" at 3018,2250.99 h30 r270
  text "VC3.3" at 3112,2250.99 h30 r270
  text "INT" at 5139,2224 h30
  text "GND" at 5735,2223 h30
  text "I2C1_SDA" at 5459,2222 h30
  text "RX" at 2803,2221 h30
  text "TX" at 2910,2221 h30
  text "VC3.3" at 5822,2038 h30
  text "I2C1_SCL" at 5565,2037 h30
  text "B13" at 3578,2031 h30
  text "B15" at 3682,2031 h30
  text "C7" at 3798,2031 h30
  text "C9" at 3896,2031 h30
  text "A9" at 3995,2031 h30
  text "A13" at 4085,2031 h30
  text "A15" at 4190,2031 h30
  text "C11" at 4295,2031 h30
  text "D2" at 4405,2031 h30
  text "B4" at 4502,2031 h30
  text "B6" at 4598,2031 h30
  text "B8" at 4701,2031 h30
  text "GND" at 4837,2031 h30
  text "VC5" at 4994,2031 h30
Mechanical 1:
  lines w10: 2750,2000 2750,4170 6293.31,4170 6293.31,2000 2750,2000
